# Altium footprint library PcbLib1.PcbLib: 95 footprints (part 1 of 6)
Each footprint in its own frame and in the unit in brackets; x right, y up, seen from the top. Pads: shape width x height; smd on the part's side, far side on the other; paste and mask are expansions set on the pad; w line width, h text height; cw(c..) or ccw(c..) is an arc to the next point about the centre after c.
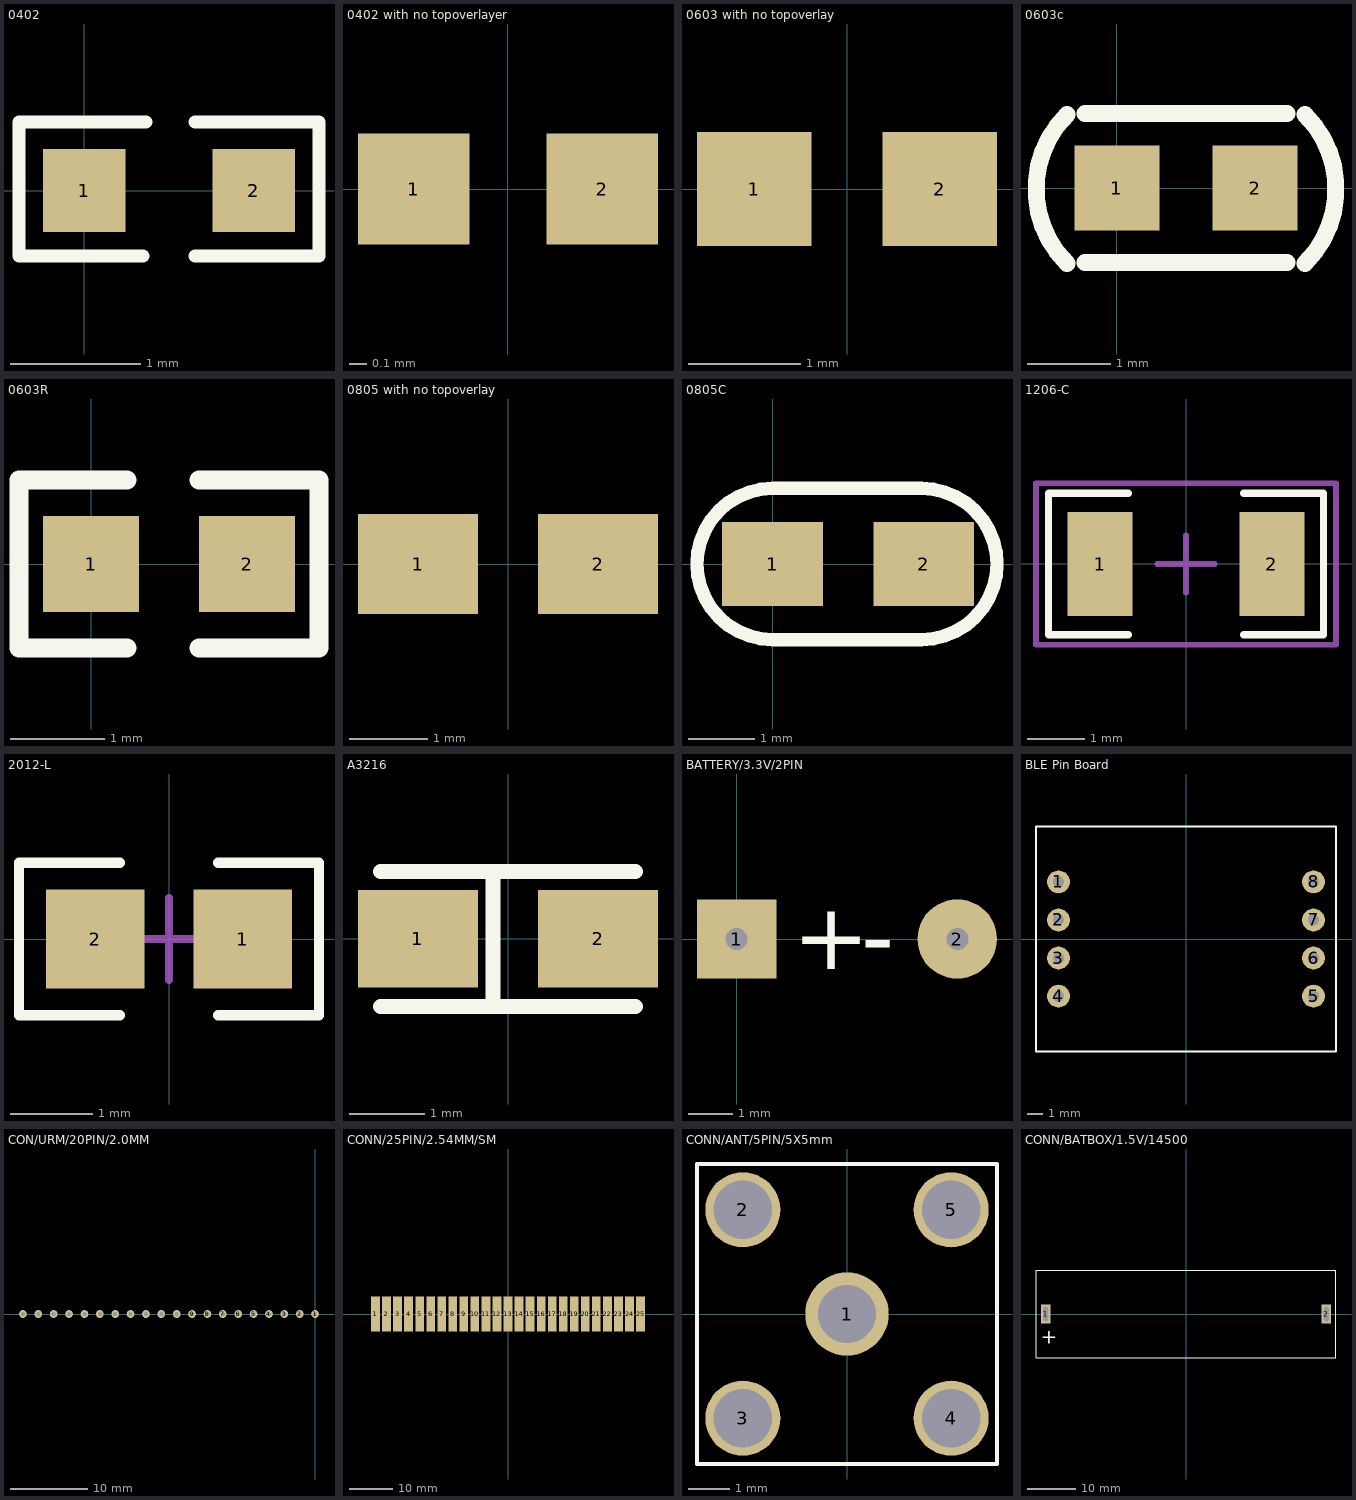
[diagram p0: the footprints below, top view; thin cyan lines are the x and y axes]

## 0402 [mm]
pads (2):
  rect 0.635x0.635 smd: 1(0,0) 2(1.3,0)
Top Overlay:
  lines w0.1: 0.45,-0.5 -0.5,-0.5 -0.5,0.525 0.475,0.525 ; 0.85,-0.5 1.8,-0.5 1.8,0.525 0.85,0.525

## 0402 with no topoverlayer [mm]
pads (2):
  rect 0.65x0.65 smd mask+0.05: 1(-0.55,0) 2(0.55,0)

## 0603 with no topoverlay [mil]
pads (2):
  rect 40x40 smd: 1(-32.5,0) 2(32.5,0)

## 0603c [mil]
pads (2):
  rect 40x40 smd: 1(0,0) 2(65,0)
Top Overlay:
  lines w8: -23.62,-35.43 cw(c11.38,-0.43) -23.62,34.57 ; -15,-35 80,-35 ; -15,35 80,35 ; 88.58,-35.43 ccw(c53.58,-0.43) 88.58,34.57
3D body: height 23.62, standoff 0, extent 0.51,-15.74 63.5,15.75

## 0603R [mil]
pads (2):
  rect 40x40 smd: 1(0,0) 2(65,0)
Top Overlay:
  lines w8: 15,-35 -30,-35 -30,35 15,35 ; 45,-35 95,-35 95,35 45,35
3D body: height 11.89, standoff 0, extent 0.51,-15.74 63.5,15.75

## 0805 with no topoverlay [mil]
pads (2):
  rect 60x50 smd: 1(-45,0) 2(45,0)

## 0805C [mil]
pads (2):
  rect 60x50 smd: 1(0,0) 2(90,0)
Top Overlay:
  lines w8: 65,45 88.58,45 cw(c88.58,0) 88.58,-45 65,-45 0,-45 cw(c0,0) 0,45 70,45
3D body: height 47.24, standoff 0, extent 5.63,-23.62 84.37,23.62

## 1206-C [mm]
pads (2):
  rect 1.13x1.8 smd: 1(-1.49,0) 2(1.49,0)
Top Overlay:
  lines w0.127: -1,-1.227 -2.382,-1.227 -2.382,1.227 -1,1.227 ; 1,-1.227 2.382,-1.227 2.382,1.227 1,1.227
Mechanical 15:
  lines w0.1: -0.5,0 0.5,0 ; 0,-0.5 0,0.5 ; -2.6,-1.4 -2.6,1.4 2.6,1.4 2.6,-1.4 -2.6,-1.4
3D body: height 1, standoff 0, extent -1.602,-0.813 1.598,0.787

## 2012-L [mm]
pads (2):
  rect 1.2x1.2 smd: 1(0.9,0) 2(-0.9,0)
Top Overlay:
  lines w0.127: -0.6,-0.927 -1.827,-0.927 -1.827,0.927 -0.6,0.927 ; 0.6,-0.927 1.827,-0.927 1.827,0.927 0.6,0.927
Mechanical 15:
  lines w0.1: -0.5,0 0.5,0 ; 0,-0.5 0,0.5
3D body: height 1.2, standoff 0, extent -1,-0.65 1,0.65

## A3216 [mm]
pads (2):
  rect 1.6x1.3 smd paste+0 mask+0.1: 1(-1.2,0) 2(1.2,0)
Top Overlay:
  lines w0.2: -1.7,-0.9 1.7,-0.9 ; -1.7,0.9 1.7,0.9 ; -0.203,-0.838 -0.203,0.813

## BATTERY/3.3V/2PIN [mm]
pads (2):
  rect 1.8x1.8 hole 0.5: 1(0,0)
  round 1.8 hole 0.5: 2(5,0)
Top Overlay:
  text "+" at 1.27,-0.686 h1.52
  text "-" at 2.819,-0.686 h1.52

## BLE Pin Board [mil]
pads (8):
  round 60 hole 30: 1(-334.65,150) 2(-334.65,50) 3(-334.65,-50) 4(-334.65,-150) 5(334.65,-150) 6(334.65,-50) 7(334.65,50) 8(334.65,150)
Top Overlay:
  lines w5: -393.7,-295.28 393.7,-295.28 393.7,295.28 -393.7,295.28 -393.7,-295.28

## CON/URM/20PIN/2.0MM [mil]
pads (20):
  round 40 hole 20 mask+2.5: 1(0,0) 2(-78.74,0) 3(-157.48,0) 4(-236.22,0) 5(-314.96,0) 6(-393.7,0) 7(-472.44,0) 8(-551.18,0) 9(-629.92,0) 10(-708.66,0) 11(-787.4,0) 12(-866.14,0) 13(-944.88,0) 14(-1023.62,0) 15(-1102.36,0) 16(-1181.1,0) 17(-1259.84,0) 18(-1338.58,0) 19(-1417.32,0) 20(-1496.06,0)

## CONN/25PIN/2.54MM/SM [mm]
pads (25):
  rect 2x8 smd: 1(-30.48,0) 2(-27.94,0) 3(-25.4,0) 4(-22.86,0) 5(-20.32,0) 6(-17.78,0) 7(-15.24,0) 8(-12.7,0) 9(-10.16,0) 10(-7.62,0) 11(-5.08,0) 12(-2.54,0) 13(0,0) 14(2.54,0) 15(5.08,0) 16(7.62,0) 17(10.16,0) 18(12.7,0) 19(15.24,0) 20(17.78,0) 21(20.32,0) 22(22.86,0) 23(25.4,0) 24(27.94,0) 25(30.48,0)

## CONN/ANT/5PIN/5X5mm [mm]
pads (5):
  round 2 hole 1.4: 1(0,0)
  round 1.8 hole 1.4: 2(-2.5,2.5) 3(-2.5,-2.5) 4(2.5,-2.5) 5(2.5,2.5)
Top Overlay:
  lines w0.1: -3.6,-3.6 -3.6,3.6 3.6,3.6 3.6,-3.6 -3.6,-3.6

## CONN/BATBOX/1.5V/14500 [mm]
pads (2):
  rect 2x4 hole 1 slot 3 at 90 deg: 1(-29,0) 2(29,0)
Top Overlay:
  lines w0.254: -31,-9 -31,0 -31,9 31,9 31,-9 -31,-9
  text "+" at -29.991,-6.121 h3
